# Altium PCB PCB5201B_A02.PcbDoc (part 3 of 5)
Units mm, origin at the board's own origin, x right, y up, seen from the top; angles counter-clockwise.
Board outline 115 x 60 mm, 6 copper layers (Top Layer, GND Layer 2, Signal Layer 3, Signal Layer 4, VCC Layer 5, Bottom Layer), stack 1.555 mm thick; 355 components, 250 nets, 1223 pads, 1070 vias.
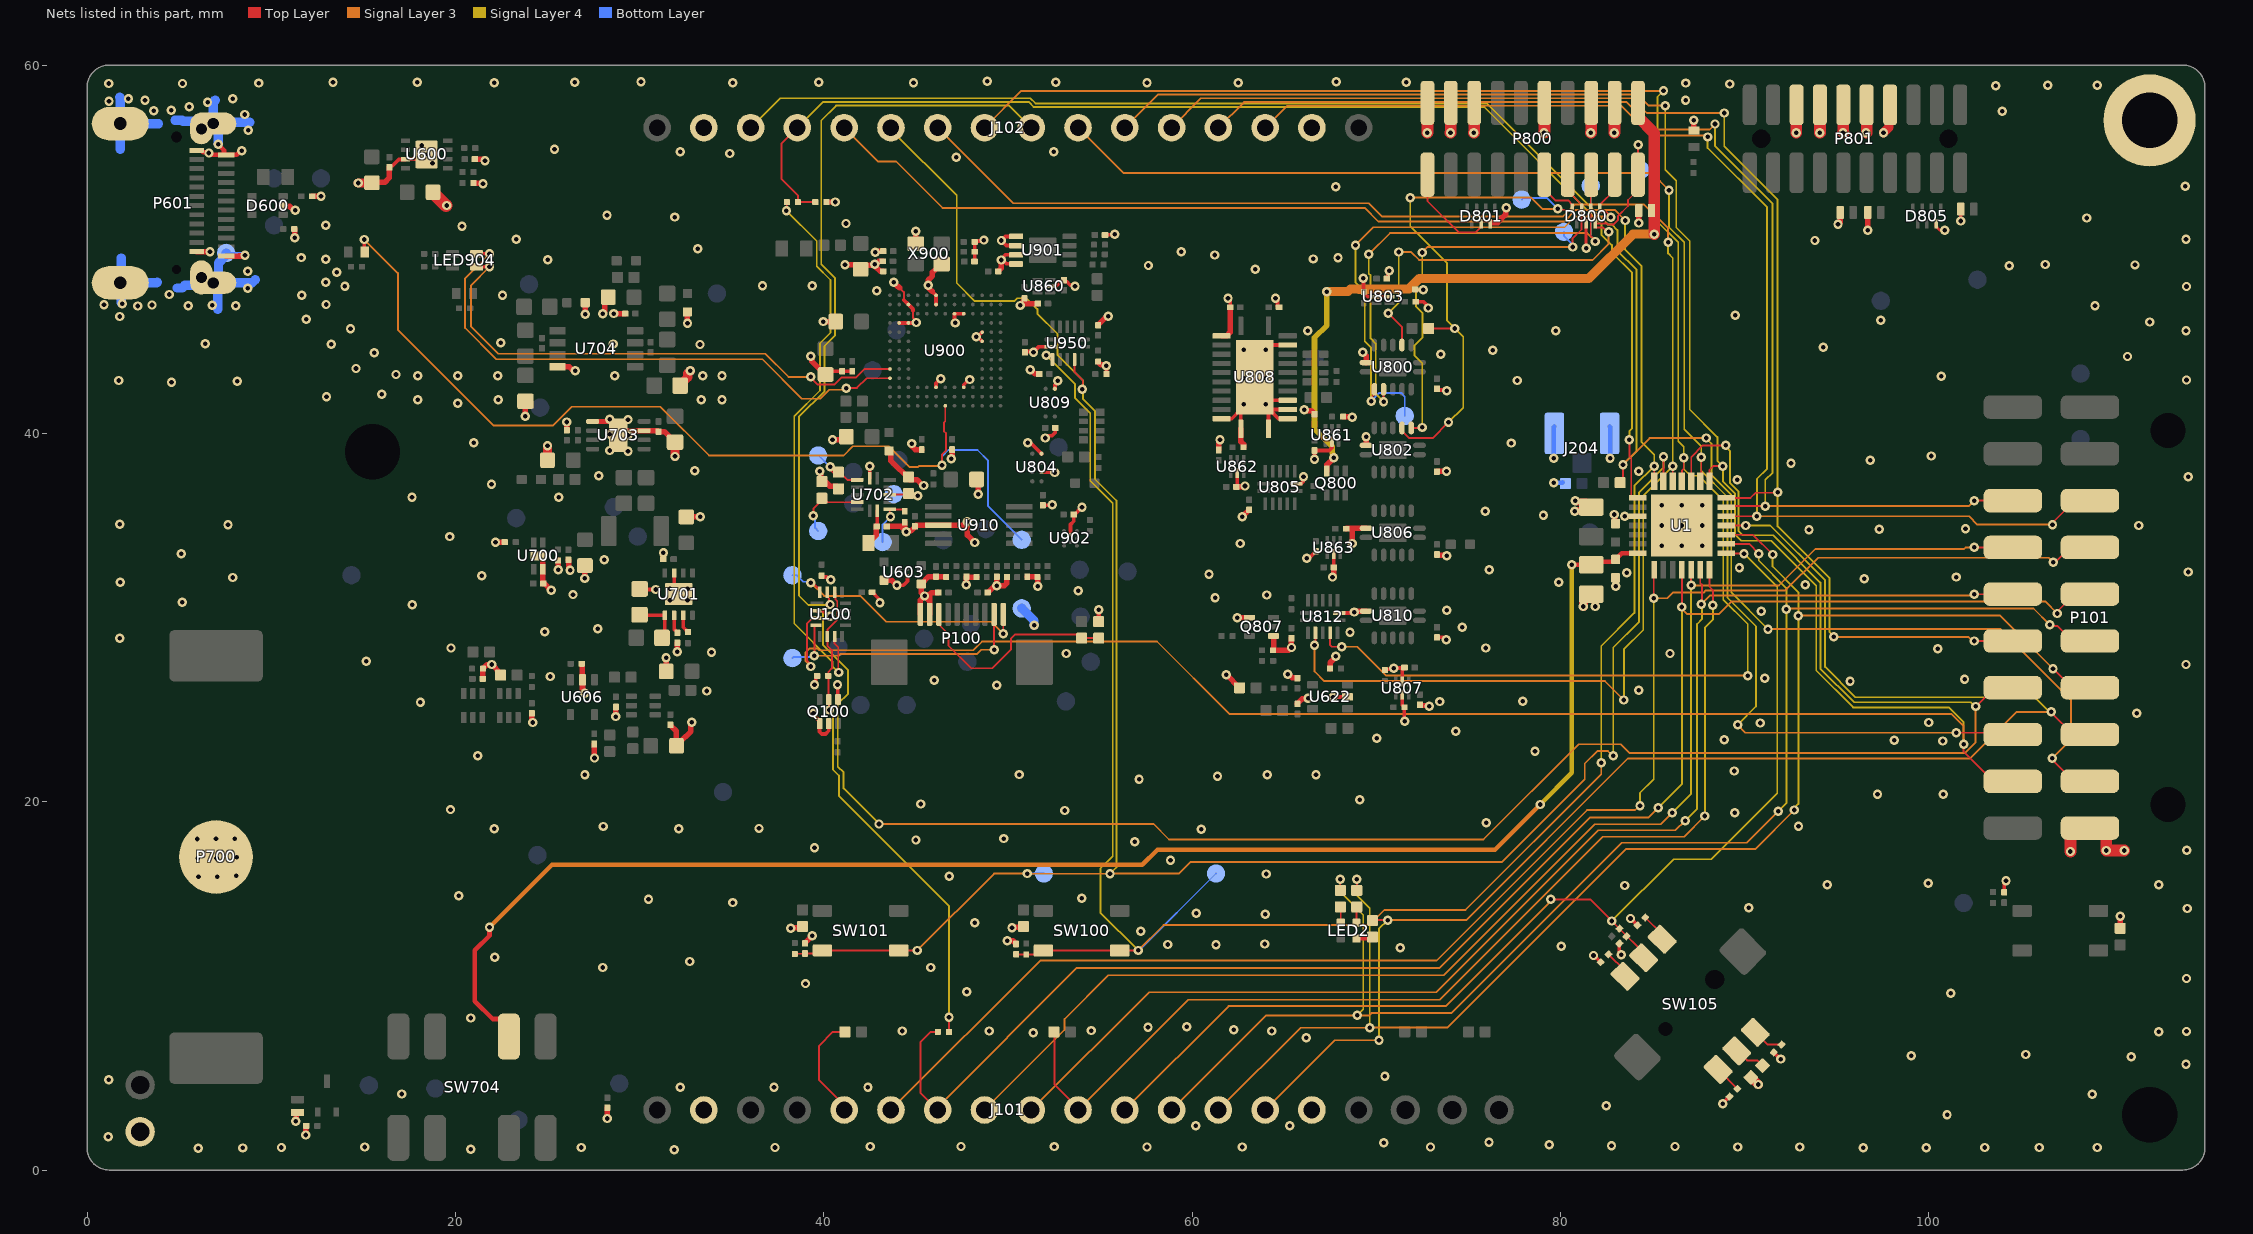
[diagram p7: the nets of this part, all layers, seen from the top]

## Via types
v1: diameter 0.508, hole 0.25, Top Layer to Bottom Layer, tented both sides, 1070 vias

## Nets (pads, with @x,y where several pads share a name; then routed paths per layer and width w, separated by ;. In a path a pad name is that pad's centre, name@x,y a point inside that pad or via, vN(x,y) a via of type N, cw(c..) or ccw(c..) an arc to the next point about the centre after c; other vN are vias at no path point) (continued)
DEBUG_TRACED3: D801.6 P800.20 | length 5.3
  Top Layer w0.1: P800.20@72.785,54.05 72.785,52.615 74.475,50.925 75.4,50.925 75.7,51.225 D801.6@75.7,51.385
DH_#RESET: D800.4 P800.10 R816.1 TPJ811.1 U802.3 | length 32.5
  Top Layer w0.1: U802.3@71.4,40.3 71.4,40.15 71.8,39.75 73.075,39.75 v1(73.925,40.6) ; R816.1@72.85,45.7 v1@74.175,45.7 ; P800.10@79.135,54.05 79.135,53.24 79.725,52.65 80.425,52.65 80.65,52.425 D800.4@80.65,52.215 80.585,52.15 79.896,52.15 v1(79.85,52.196)
  Signal Layer 3 w0.1: v1(71.85,52.807) 78.418,52.807 79.029,52.196 v1(79.85,52.196)
  Signal Layer 4 w0.1: v1(71.85,52.807) 71.85,51.25 73.85,49.25 73.85,46.125 v1(74.275,45.7) 74.725,45.25 74.725,41.4 v1(73.925,40.6)
  Bottom Layer w0.1: TPJ811.1@77.9,52.7 77.993,52.793 79.263,52.793 79.85,52.206 v1(79.85,52.196)
DH_TCK_SWCLK: D800.1 P800.4 TPJ818.1 U800.9 | length 30.3
  Top Layer w0.1: v1(69.725,41.75) 69.725,41.95 69.9,42.125 U800.9@69.9,42.4 ; v1(82.732,51.746) 82.732,51.796 82.509,52.019 82.195,52.019 82.15,52.064 82.15,52.425 82.945,53.22 P800.4@82.945,54.05
  Signal Layer 3 w0.1: v1(68.875,50.225) 69.85,51.2 80.225,51.2 80.797,51.772 82.706,51.772 v1(82.732,51.746)
  Signal Layer 4 w0.1: v1(68.875,50.225) 68.875,48.2 69.375,47.7 69.375,45 69.725,44.65 v1(69.725,41.75)
  Bottom Layer w0.1: v1(69.725,41.75) 70.175,42.2 71.35,42.2 71.55,42 TPJ818.1@71.55,40.95
DH_TDI: D800.3 P800.8 TPJ820.1 U802.2 | length 24.5
  Top Layer w0.1: U802.2@71.9,40.3 72.475,40.3 v1(72.5,40.325) ; P800.8@80.405,54.05 80.405,53.17 81.15,52.425 81.15,51.074 80.655,50.579 80.655,50.145 v1(80.675,50.125)
  Signal Layer 3 w0.1: v1(72.5,49.825) 72.8,50.125 v1(80.675,50.125)
  Signal Layer 4 w0.1: v1(72.5,40.325) 72.5,43.8 72.082,44.218 72.082,44.782 72.518,45.218 72.518,46.538 72.167,46.889 72.167,48.092 72.5,48.425 v1(72.5,49.825)
  Bottom Layer w0.1: TPJ820.1@80.2,50.95 80.2,50.71 80.675,50.235 v1(80.675,50.125)
DH_TDO_SWO: D800.2 P800.6 TPJ812.1 U800.10 | length 28.7
  Top Layer w0.1: v1@70.4,41.825 U800.10@70.4,42.4 ; P800.6@81.675,54.05 81.65,54.025 D800.2@81.65,52.215 81.65,50.746 81.9,50.496 v1(81.9,50.425)
  Signal Layer 3 w0.1: v1(69.6,49.725) 70.75,50.875 81.45,50.875 v1(81.9,50.425)
  Signal Layer 4 w0.1: v1(69.6,49.725) 69.6,48.681 69.693,48.588 69.693,45.157 69.975,44.875 69.975,42.15 v1(70.4,41.725)
  Bottom Layer w0.1: TPJ812.1@81.65,53.45 81.65,50.746 81.9,50.496 v1(81.9,50.425)
DH_TMS_SWDIO: D800.7 P800.2 TPJ814.1 U800.3 | length 26.6
  Top Layer w0.1: v1(70.663,46.527) 71.4,45.79 U800.3@71.4,44.8 ; v1(82.623,50.96) 82.524,50.96 82.295,51.189 81.945,51.189 81.9,51.234 81.9,51.445 81.945,51.4 82.525,51.4 82.572,51.353 82.898,51.353 83.128,51.583 83.128,51.803 83.675,52.35 83.675,52.675 84.215,53.215 P800.2@84.215,54.05 84.215,55.665 v1(84.225,55.675)
  Signal Layer 3 w0.1: v1(71.225,49.85) 71.899,49.85 72.331,49.418 81.752,49.418 82.623,50.289 v1(82.623,50.96)
  Signal Layer 4 w0.1: v1(70.663,46.527) 71.225,47.089 v1(71.225,49.85)
  Bottom Layer w0.1: v1(84.225,55.675) 84.225,54.425 TPJ814.1@84.35,54.3
DH_VTREF: D809.1 P800.1 Q800.3 | length 37.2
  Top Layer w0.3: Q800.3@67.325,37.95 67.325,38.3 v1(67.7,38.675)
  Top Layer w0.635: P800.1@84.215,57.95 84.215,57.193 85.1,56.309 v1(85.1,50.825)
  Signal Layer 3 w0.5: v1(67.318,47.702) 68.463,47.702 68.612,47.85 69.037,47.85 69.054,47.832 69.546,47.832 69.563,47.85 71.776,47.85 72.339,48.413 81.538,48.413 83.95,50.825 v1(85.1,50.825)
  Signal Layer 4 w0.3: v1(67.318,47.702) 67.318,45.868 66.65,45.2 66.65,40.25 67.61,39.29 67.61,38.912 67.66,38.862 67.66,38.715 v1(67.7,38.675)
  Bottom Layer w0.5: v1(67.318,47.702) v1(67.318,47.702)
DISP_CS: R301.1 U100.7 | length 30.4
  Top Layer w0.1: v1(37.975,52.1) 37.988,52.113 37.988,52.513 R301.1@38.05,52.575 ; U100.7@40.59,28.975 40.59,28.579 40.79,28.379 40.79,27.039 v1(40.807,27.021)
  Signal Layer 4 w0.1: v1(37.975,52.1) 39.625,50.45 39.625,49.075 40.368,48.332 40.368,45.468 39.799,44.899 39.799,42.332 38.4,40.933 38.4,29.677 40.47,27.607 40.47,27.358 v1(40.807,27.021)
DISP_ENABLE: Q100.2 R141.2 R303.1 U100.6 U100.14 | length 27.1
  Top Layer w0.1: v1(40.297,24.98) 40.286,24.991 40.286,25.529 40.246,25.569 40.258,25.581 40.258,26.816 R141.2@40.242,26.832 40.244,26.834 40.244,27.039 40.443,27.237 40.443,28.232 40.2,28.475 40.2,28.965 U100.6@40.19,28.975 40.208,28.993 40.208,29.358 40.737,29.887 40.737,30.888 40.64,30.985 40.64,31.325 U100.14@40.59,31.375 ; R303.1@46.8,7.5 v1(46.8,8.3)
  Signal Layer 4 w0.1: v1(40.297,24.98) 40.297,24.921 40.5,24.718 40.5,21.75 40.825,21.425 40.825,20.325 46.8,14.35 v1(46.8,8.3)
DISP_SCLK: J102.9 P101.8 U1.24 U100.15 | length 150.5
  Top Layer w0.1: U100.15@40.19,31.375 40.24,31.325 40.24,31.085 40.294,31.031 40.294,30.758 v1(40.344,30.709) ; U1.24@87.1,37.275 87.113,37.287 87.113,38.718 87.744,39.35 v1(88.975,39.35) ; v1(102.55,25.175) 102.576,25.175 103.591,26.19 P101.8@104.57,26.19
  Signal Layer 3 w0.1: v1(43.003,18.793) 57.907,18.793 58.75,17.95 75.825,17.95 80.993,23.118 83.282,23.118 83.75,22.65 101.981,22.65 102.55,23.219 v1(102.55,25.175)
  Signal Layer 4 w0.1: v1@40.313,30.678 39.172,30.678 38.65,31.2 38.65,40.9 40.05,42.3 40.05,44.75 40.62,45.32 40.62,48.43 39.866,49.184 39.866,56.991 40.675,57.8 50.072,57.8 J102.9@51.27,56.602 ; v1(40.344,30.709) 39.951,30.316 39.951,28.524 41.325,27.15 41.325,25.875 40.763,25.313 40.763,21.912 41.075,21.6 41.075,20.721 v1(43.003,18.793) ; v1(88.975,39.35) 88.975,39.264 89.218,39.022 89.218,38.062 89.207,38.051 89.207,37.312 89.682,36.837 89.682,34.693 89.9,34.475 91.55,34.475 94.125,31.9 94.125,27.225 95.95,25.4 102.287,25.4 102.512,25.175 v1(102.55,25.175)
DISP_SI: J102.11 P101.4 U1.22 U100.3 | length 151
  Top Layer w0.1: 39.24,29.825 39.1,29.685 39.1,27.656 39.304,27.452 v1(39.304,27.342) ; 39.24,29.825 39.39,29.975 U100.3@39.59,29.975 ; U1.22@88.1,37.275 88.1,38.025 88.3,38.225 v1@88.75,38.225 ; v1(101.9,23.125) 101.9,22.725 103.515,21.11 P101.4@104.57,21.11
  Signal Layer 3 w0.1: v1(39.304,27.342) 39,27.645 39,28.1 39.218,28.318 39.671,28.318 39.764,28.225 48.125,28.225 48.6,28.7 58.098,28.7 62.028,24.769 101.231,24.769 101.9,24.1 v1(101.9,23.125) ; J102.11@56.35,56.602 58.146,58.398 84.202,58.398 84.8,57.8 v1(85.7,57.8)
  Signal Layer 4 w0.1: v1(85.7,57.8) 85.7,54.317 86.293,53.724 86.293,51.182 87.025,50.45 87.025,41.3 88.525,39.8 88.525,38.525 v1(88.825,38.225) 88.825,37.412 89.482,36.754 89.482,34.518 89.825,34.175 91.456,34.175 93.9,31.731 93.9,27.125 95.9,25.125 101.1,25.125 101.9,24.325 v1(101.9,23.125)
EFM_VREGIN: C3.1 C4.1 SW704.7 U1.7 | length 84.7
  Top Layer w0.25: v1(21.85,13.175) 21.85,12.725 21.05,11.925 21.05,9.175 22.023,8.202 22.438,8.202 22.9,7.741 SW704.7@22.9,7.25 ; v1(80.625,32.875) 80.628,32.872 81.672,32.872 C3.1@81.675,32.869 ; C3.1@81.725,33.1 81.788,33.037 82.875,33.037 C4.1@83,33.162 83.338,33.5 U1.7@84.325,33.5
  Signal Layer 3 w0.25: v1(21.85,13.175) 25.243,16.568 57.293,16.568 58.125,17.4 76.45,17.4 v1(78.9,19.85)
  Signal Layer 4 w0.25: v1(78.9,19.85) 80.625,21.575 v1(80.625,32.875)
EXP_HEADER5: J101.14 P101.5 R135.2 U1.18 | length 83.4
  Top Layer w0.1: R135.2@69.8,13.55 69.85,13.6 69.878,13.572 v1(70.628,13.572) ; U1.18@88.875,35 v1(90.075,35) ; v1(106.658,24.881) 106.658,24.84 107.848,23.65 P101.5@108.76,23.65
  Signal Layer 3 w0.1: J101.14@63.97,3.262 67.758,7.05 v1(70.15,7.05) ; v1(70.628,13.572) 74.897,13.572 83.675,22.35 102.25,22.35 104.781,24.881 v1(106.658,24.881)
  Signal Layer 4 w0.1: v1(70.15,7.05) 70.15,13.094 v1(70.628,13.572) ; v1(90.075,35) 91.4,35 94.375,32.025 94.375,27.325 96.025,25.675 105.75,25.675 106.466,24.959 106.469,24.959 v1@106.6,24.828
EXP_HEADER6: J102.10 P101.6 U1.23 | length 81.5
  Top Layer w0.1: U1.23@87.6,37.275 87.65,37.325 v1(87.65,38.7) ; v1(101.5,23.75) 104.47,23.75 P101.6@104.57,23.65
  Signal Layer 3 w0.1: J102.10@53.81,56.602 56.262,54.15 84.957,54.15 v1(85.9,53.207) ; v1(89.625,24.175) 90.052,23.748 101.498,23.748 v1(101.5,23.75)
  Signal Layer 4 w0.1: v1(85.9,53.207) 85.9,51.2 86.725,50.375 86.725,40.225 87.65,39.3 v1(87.65,38.7) 87.65,37.975 89.077,36.548 89.077,31.073 90.625,29.525 90.625,25.175 v1(89.625,24.175)
EXP_HEADER7: J101.13 P101.7 R136.2 U1.17 | length 82.1
  Top Layer w0.1: R136.2@68.944,15.184 68.95,15.191 v1(68.95,15.8) ; U1.17@88.875,34.5 90.45,34.5 v1(91.525,33.425) ; v1(106.753,27.229) 106.761,27.229 107.8,26.19 P101.7@108.76,26.19
  Signal Layer 3 w0.1: J101.13@61.43,3.262 65.893,7.725 v1(69.65,7.725) 69.657,7.732 73.857,7.732 83.55,17.425 90.575,17.425 v1(92.7,19.55) ; v1(92.925,30.1) 92.943,30.118 103.864,30.118 v1(106.753,27.229)
  Signal Layer 4 w0.1: v1(68.95,15.8) 68.95,14.925 69.65,14.225 v1(69.65,7.725) ; v1(91.525,33.425) 91.525,32.775 92.925,31.375 v1(92.925,30.1) 92.925,19.885 92.7,19.66 v1(92.7,19.55)
EXP_HEADER9: J101.12 P101.9 R137.2 U1.16 | length 82.4
  Top Layer w0.1: v1(68.05,15.8) 68.05,15.189 R137.2@68.052,15.187 ; U1.16@88.875,34 90.25,34 v1(90.775,33.475) ; v1(106.584,29.602) 106.636,29.55 106.988,29.55 107.808,28.73 P101.9@108.76,28.73
  Signal Layer 3 w0.1: J101.12@58.89,3.262 64.028,8.4 v1(68.975,8.4) v1@69,8.4 ; v1@69.05,8.4 69.625,8.4 69.75,8.525 74.075,8.525 83.325,17.775 90.125,17.775 v1(91.825,19.475) ; v1(92.275,30.45) 92.318,30.493 105.693,30.493 v1(106.584,29.602)
  Signal Layer 4 w0.1: v1(68.05,15.8) 68.05,15.1 69.3,13.85 69.3,8.725 v1(68.975,8.4) ; v1(90.775,33.475) 90.775,33.1 92.275,31.6 v1(92.275,30.45) 92.275,19.925 v1(91.825,19.475)
EXP_HEADER10: J102.12 P101.10 U1.21 | length 74.8
  Top Layer w0.1: U1.21@88.875,36.5 90.325,36.5 90.6,36.775 91.775,36.775 v1(91.8,36.8) ; v1(102.47,28.73) P101.10@104.57,28.73
  Signal Layer 3 w0.1: J102.12@58.89,56.602 60.485,58.197 83.903,58.197 84.7,57.4 v1(88.9,57.4) ; v1(94.85,28.95) 102.14,28.95 102.36,28.73 v1(102.47,28.73)
  Signal Layer 4 w0.1: v1(88.9,57.4) 88.9,55.595 91.8,52.695 v1(91.8,36.8) 91.8,34.95 94.625,32.125 94.625,29.213 94.85,28.988 v1(94.85,28.95)
EXP_HEADER11: J101.7 P101.11 R303.2 U1.11 | length 88.3
  Top Layer w0.1: J101.7@46.19,3.262 45.25,4.202 45.25,6.95 45.8,7.5 R303.2@46.2,7.5 ; v1(86.6,30.575) U1.11@86.6,32.725 ; v1(106.977,30.222) 106.977,30.331 107.916,31.27 P101.11@108.76,31.27
  Signal Layer 3 w0.1: J101.7@46.19,3.262 46.19,3.415 53.75,10.975 73.45,10.975 81.625,19.15 84.8,19.15 v1(85.325,19.675) ; v1(86.6,30.575) 86.6,30.467 86.867,30.2 88.625,30.2 89.3,30.875 106.324,30.875 v1(106.977,30.222)
  Signal Layer 4 w0.1: v1(85.325,19.675) 86.6,20.95 v1(86.6,30.575)
EXP_HEADER12: J101.9 P101.12 U1.13 | length 73.4
  Top Layer w0.1: U1.13@87.6,32.725 87.6,31.875 87.7,31.775 87.7,30.775 v1(87.65,30.725) ; v1(102.47,31.27) P101.12@104.57,31.27
  Signal Layer 3 w0.1: J101.9@51.27,3.262 57.665,9.657 73.257,9.657 82.05,18.45 86.25,18.45 v1(86.775,18.975) ; v1(87.65,30.725) 88.117,31.192 102.392,31.192 v1(102.47,31.27)
  Signal Layer 4 w0.1: v1(86.775,18.975) 87.425,19.625 87.425,29.65 87.7,29.925 87.7,30.675 v1(87.65,30.725)
EXP_HEADER13: J101.6 P101.13 U1.8 | length 85.8
  Top Layer w0.1: v1(85.075,31.05) 85.075,32.7 U1.8@85.1,32.725 ; v1(106.775,33) 106.885,33 107.745,33.86 P101.13@108.8,33.86
  Signal Layer 3 w0.1: J101.6@43.65,3.262 51.763,11.375 73.275,11.375 81.45,19.55 84.062,19.55 84.287,19.775 v1(84.325,19.775) ; v1@85.2,31.025 85.225,31.05 85.8,31.05 86.107,31.357 87.782,31.357 87.9,31.475 92.225,31.475 94,33.25 106.525,33.25 v1(106.775,33)
  Signal Layer 4 w0.1: v1(84.325,19.775) 84.325,20.48 85.075,21.23 v1(85.075,31.05)
EXP_HEADER14: J101.8 P101.14 U1.12 | length 76.4
  Top Layer w0.1: v1(87.1,31.75) U1.12@87.1,32.725 ; v1(102.47,33.81) P101.14@104.57,33.81
  Signal Layer 3 w0.1: J101.8@48.73,3.262 53.075,7.607 53.075,8.2 55.45,10.575 73.675,10.575 81.875,18.775 85.45,18.775 v1(86.075,19.4) ; v1(87.1,31.75) 91.875,31.75 93.85,33.725 101.925,33.725 102.01,33.81 v1(102.47,33.81)
  Signal Layer 4 w0.1: v1(86.075,19.4) 87.1,20.425 v1@87.1,31.7
EXP_HEADER15: J102.14 P101.15 U1.19 | length 68.1
  Top Layer w0.1: U1.19@88.875,35.5 v1(90.675,35.5) ; v1(106.725,35.05) 106.725,35.159 107.966,36.4 P101.15@108.8,36.4
  Signal Layer 3 w0.1: J102.14@63.97,56.602 65.162,57.794 83.306,57.794 84.922,56.178 87.922,56.178 v1(88,56.1) ; v1(90.675,35.5) 102.2,35.5 102.65,35.05 v1(106.725,35.05)
  Signal Layer 4 w0.1: v1(88,56.1) 88,55.5 91.225,52.275 91.225,38.075 90.675,37.525 v1(90.675,35.5)
EXP_HEADER16: J102.13 P101.16 U1.20 | length 66.3
  Top Layer w0.1: U1.20@88.875,36 88.925,36.05 v1(91.125,36.05) ; v1(102.47,36.35) P101.16@104.57,36.35
  Signal Layer 3 w0.1: J102.13@61.43,56.602 62.823,57.995 83.605,57.995 85.1,56.5 88.1,56.5 v1(88.4,56.8) ; v1(91.125,36.05) 102.17,36.05 v1(102.47,36.35)
  Signal Layer 4 w0.1: v1(88.4,56.8) 88.4,55.6 91.525,52.475 91.525,37.875 91.125,37.475 v1(91.125,36.05)
GND: C1.2 C2.2 C3.2 C4.2 C8.2 C102.2 C103.2 C104.2 C106.2 C143.2 C144.2 C600.2 C602.2 C607.2 C608.2 C609.2 C610.2 C611.2 C621.2 C625.2 C632.2 C635.2 C638.2 C641.2 C652.2 C653.2 C655.2 C660.2 C673.2 C674.2 C700.2 C701.2 C702.2 C703.2 C705.2 C706.2 C707.2 C708.2 C714.2 C720.2 C724.2 C728.2 C729.2 C730.2 C731.2 C800.2 C803.2 C804.2 C805.2 C806.2 C807.2 C808.2 C809.2 C810.2 C827.2 C828.2 C860.2 C861.2 C862.2 C863.2 C864.2 C865.2 C866.2 C867.2 C868.2 C869.2 C870.2 C900.2 C901.2 C902.2 C903.2 C904.2 C905.2 C906.2 C907.2 C908.2 C909.2 C910.2 C911.2 C914.2 C921.2 C922.2 C924.2 C925.2 C926.2 C927.2 C950.2 C951.2 D600.2 D703.2 D800.6 D801.7 D805.7 D806.2 D807.2 D808.2 D809.2 J101.2 J101.15 J102.2 J102.15 J204.2 J204.3 LED900.2 M1.1 P100.1 P100.2 P101.1 P601.25@1.8,56.82 P601.26@1.8,48.18 P601.27@6.2,56.525 P601.27@6.85,56.82 P601.28@6.2,48.475 P601.28@6.85,48.18 P601.A1 P601.A12 P601.B1 P601.B12 P700.2 P800.3 P800.5 P800.9 P800.15 P800.17 P800.19 P801.7 P801.9 P801.11 P801.13 P801.15 Q100.1 Q100.4 Q100.5 Q807.1 Q807.4 R7.1 R104.2 R105.2 R113.1 R124.1 R125.1 R126.1 R127.1 R140.1 R141.1 R146.1 R220.1 R302.1 R602.1 R620.1 R621.1 R623.1 R628.2 R631.1 R634.1 R637.1 R640.1 R674.2 R688.2 R691.2 R703.1 R705.1 R706.1 R707.1 R708.1 R718.1 R760.1 R763.1 R767.1 R771.1 R792.1 R807.2 R808.2 R814.1 R817.1 R839.1 R850.1 R851.1 R852.1 R853.1 R930.2 R931.2 R950.2 R981.2 ST701.1 TPJ614.1 TPJ913.1 U1.3 U1.29 U100.2 U600.3 U600.9 U603.A1 U606.2 U622.2 U700.2 U700.5 U701.3 U701.9 U702.7 U703.3 U703.5 U703.9 U704.4 U800.7 U802.7 U803.2 U803.5 U804.B1 U804.D1 U805.7 U806.7 U807.2 U807.5 U808.2 U808.11 U808.12 U808.13 U808.14 U808.15 U808.16 U808.22 U808.25 U809.D1 U810.7 U812.7 U860.2 U861.2 U862.2 U863.2 U900.C5 U900.C8 U900.H3 U900.J3 U900.K11 U900.K12 U900.L5 U900.L6 U900.M8 U900.M11 U900.N8 U901.1 U901.2 U901.3 U901.4 U902.B2 U910.3 U950.7 X900.2 X900.4 | length 231.3
  Top Layer w0.1: 44.125,47.9 44.35,47.675 44.35,47.25 ; 44.85,46.674 44.85,46.275 v1@45.025,46.1
  Top Layer w0.15: v1(81.4,50.05) D800.6@81.4,51.385 ; D805.7@100.4,51.385 100.4,51.25 100.6,51.05 v1@101.05,51.05
  Top Layer w0.2: C600.2@16.417,54.451 16.417,54.471 16.477,54.531 16.581,54.531 16.922,54.872 17.257,54.872 U600.3@17.282,54.897 U600.9@18.182,54.897 ; R703.1@30.105,31.556 30.135,31.525 v1(30.875,31.525) ; U701.9@31.725,31.575 31.875,31.725 U701.3@31.875,32.425 ; v1(39.446,24.8) 39.446,24.719 39.775,24.39 Q100.4@39.775,24.24 39.775,23.8 39.9,23.675 40.1,23.675 40.275,23.85 Q100.5@40.275,24.24 ; v1(39.498,26.353) 39.498,26.437 39.572,26.511 39.572,26.772 39.632,26.832 R141.1@39.642,26.832 ; U100.2@39.59,30.375 39.956,30.375 40.261,30.07 v1(40.344,30.07) ; R140.1@39.888,32.275 39.888,32.265 39.948,32.205 40.158,32.205 40.307,32.057 v1(40.39,32.057) ; C907.2@40.1,43.2 40.275,43.375 C924.2@41,43.375 C925.2@41.55,43.375 ; v1(40.75,26.35) 40.762,26.337 40.762,25.552 Q100.1@40.775,25.54 ; U702.7@42.5,37.56 v1(42.5,38.225) v1@42.65,38.225 ; C104.2@42.623,31.374 42.643,31.374 42.993,31.024 42.993,30.863 v1(43.052,30.804) ; v1(43.975,31.75) 44.325,31.75 44.55,31.975 U603.A1@44.55,32.25 ; U900.K12@44.1,46 U900.K11@44.6,46 45,46 v1(45.025,46.025) v1@45.025,46.1 ; 44.35,47.25 U900.M11@44.6,47 44.85,46.75 44.85,46.674 ; v1@45.35,37.1 v1(45.425,37.175) ; 45.885,47.71 46.095,47.5 U900.N8@46.1,47.5 U900.M8@46.1,47 ; U900.C8@46.1,42.5 46.1,42.725 v1(46.35,42.975) ; v1(47.15,46) 47.1,46.05 U900.L6@47.1,46.5 U900.L5@47.6,46.5 ; U900.C5@47.6,42.5 47.6,42.65 v1@47.875,42.925 ; C910.2@48.184,49.333 48.193,49.342 48.193,49.857 R930.2@48.201,49.865 ; R930.2@48.202,49.863 R930.2@48.201,49.865 ; v1@48.224,45.25 v1(48.275,45.25) 48.3,45.25 v1@48.325,45.275 ; U900.H3@48.6,45 v1@48.325,45.275 ; U900.J3@48.6,45.5 48.375,45.275 v1@48.325,45.275 ; v1(48.7,50.5) 48.65,50.45 48.25,50.45 R931.2@48.2,50.4 48.201,50.399 R930.2@48.201,49.865 ; v1@49.65,49.4 49.733,49.4 49.923,49.21 50.434,49.21 U901.4@50.445,49.2 ; v1@49.65,49.483 49.867,49.7 U901.3@50.445,49.7 ; U901.2@50.445,50.2 50.436,50.208 49.917,50.208 v1(49.65,50.475) 49.867,50.692 50.436,50.692 U901.1@50.445,50.7 ; C911.2@50.925,44.4 50.95,44.375 50.993,44.375 51.068,44.45 51.355,44.45 v1(51.392,44.413) ; v1@51.225,39.45 51.275,39.45 U804.D1@51.825,38.9 ; v1@51.4,44.45 51.413,44.45 51.663,44.7 U950.7@52.34,44.7 ; U804.B1@51.825,37.9 52.525,37.9 v1(52.55,37.875) ; C804.2@51.9,36.1 52.375,36.1 v1(52.4,36.125) ; v1(52.025,39.75) 52.15,39.875 52.4,39.875 52.575,40.05 C810.2@52.575,40.3 ; U860.2@52.3,48 52.625,48 52.95,48.325 C862.2@53.05,48.325 53.05,48.305 53.11,48.245 53.194,48.245 53.391,48.048 53.586,48.048 v1(53.645,47.989) ; U809.D1@52.55,42.425 52.556,42.431 52.556,42.63 52.709,42.784 v1(52.709,42.867) ; U902.B2@53.4,34.5 53.4,35.05 53.575,35.225 C914.2@53.575,35.55 ; C914.2@53.575,35.6 C914.2@53.575,35.55 ; v1(54.025,36) C914.2@53.575,35.55 ; C951.2@55.272,50.778 55.29,50.796 55.787,50.796 v1(55.805,50.814) ; R981.2@55.35,43.225 v1(55.35,43.679) ; U808.11@61.605,40.8 62.15,40.8 U808.25@62.65,41.3 ; v1(61.95,47.35) 62.075,47.225 C808.2@62.075,46.85 ; C860.2@62.4,37.1 62.45,37.15 U862.2@62.45,37.85 ; U808.12@62.65,40.255 U808.25@62.65,41.3 ; U808.25@63.425,44.55 63.675,44.8 U808.22@65.195,44.8 ; U808.13@64.15,40.255 U808.25@64.15,41.3 ; v1(64.532,47.345) 64.532,47.275 64.645,47.162 64.645,46.91 64.705,46.85 C806.2@64.725,46.85 ; U808.14@65.195,40.8 64.7,40.8 U808.25@64.2,41.3 ; U808.15@65.195,41.3 U808.25@64.2,41.3 ; U808.16@65.195,41.8 63.625,41.8 U808.25@63.4,41.575 ; U805.7@65.66,37.27 65.92,37.27 66.025,37.375 66.025,37.625 v1(66.05,37.65) ; v1(66.225,33.225) 66.35,33.225 C867.2@66.725,33.6 ; v1(66.65,38.6) C864.2@66.65,39.075 67.45,39.075 67.6,39.225 U861.2@67.6,39.55 ; v1(67.657,25.682) 67.666,25.691 68.441,25.691 U622.2@68.45,25.7 ; C866.2@67.7,32.725 U863.2@67.7,33.45 ; U812.7@67.985,30.25 68.75,30.25 v1(68.8,30.3) ; v1(69.3,48.425) 69.313,48.413 69.313,47.687 R807.2@69.325,47.675 ; R807.2@69.385,47.59 69.55,47.425 U803.2@70.025,47.425 ; U803.2@70.075,47.425 U803.5@70.725,47.425 ; R808.2@70.475,27.15 70.525,27.2 70.825,27.2 v1@70.875,27.25 ; C869.2@70.569,48.403 70.581,48.403 70.641,48.463 70.641,48.766 v1(70.7,48.825) ; v1(70.95,27.25) 70.967,27.267 71.522,27.267 C870.2@71.539,27.284 ; U807.5@71.413,25.825 71.413,25.239 71.502,25.15 R814.1@71.55,25.15 ; U807.2@71.413,26.525 71.413,27.178 71.46,27.225 C870.2@71.55,27.225 ; R814.1@71.532,25.13 71.532,24.395 v1(71.55,24.377) ; C807.2@72.125,47.825 72.14,47.81 72.545,47.81 v1(72.56,47.795) ; R817.1@72.15,47.15 72.566,47.15 72.825,46.891 v1(72.825,46.81) ; C827.2@73.3,28.925 73.675,28.925 v1(73.8,28.8) ; C803.2@73.3,42.425 73.3,42.421 73.36,42.361 73.789,42.361 v1(73.825,42.325) ; v1@73.802,37.938 v1(73.816,37.951) ; v1(81.8,11.65) 81.826,11.65 R124.1@82.188,11.288 ; C106.2@83.206,12.306 83.206,11.794 v1(83.3,11.7) ; v1(83.807,13.657) 83.833,13.657 R127.1@84.195,13.295 ; v1(88.826,3.6) 88.826,3.626 R125.1@89.188,3.988 ; R126.1@91.588,6.388 91.95,6.026 v1(91.976,6.026) ; v1@101.749,51.534 D808.2@101.748,52.181 ; C8.2@104.1,15.075 104.1,15.6 v1(104.2,15.7) ; U808.25@62.65,41.3 62.925,41.575 U808.25@63.4,41.575 ; U808.25@63.4,41.575 63.675,41.3 U808.25@64.15,41.3 ; U808.25@64.15,41.3 U808.25@64.2,41.3
  Top Layer w0.25: P601.B12@5.95,55.375 5.96,55.365 6.225,55.365 6.313,55.277 6.566,55.277 v1(6.615,55.227) ; v1@6.658,55.178 6.735,55.178 6.777,55.135 P601.A1@7.432,55.135 ; v1(7.128,55.71) 7.128,55.689 7.432,55.385 P601.A1@7.432,55.135 ; v1(8.398,55.347) 8.328,55.347 8.116,55.135 7.56,55.135 P601.A1@7.55,55.125 ; U703.5@27.45,40.65 v1@28.25,40.65 ; R302.1@40.146,52.564 40.148,52.566 40.616,52.566 v1(40.619,52.569) 40.55,52.638 v1@40.55,52.65 ; v1@54.925,30.4 54.933,30.392 54.933,29.783 R146.1@54.932,29.782 ; C868.2@72.376,25.263 72.411,25.228 72.839,25.228 v1(72.875,25.192) ; C3.2@81.25,30.919 81.6,31.269 C3.2@81.675,31.269 ; C1.2@81.699,35.824 C1.2@82.075,36.2 ; C3.2@81.9,31.1 C3.2@81.925,31.125 ; v1(83,31.7) C4.2@83,32.162 ; v1(83.5,35.5) U1.3@84.325,35.5 ; P601.A1@7.432,55.135 7.54,55.135 P601.A1@7.55,55.125 ; P601.A1@7.432,55.135 7.442,55.125 P601.A1@7.55,55.125
  Top Layer w0.27: v1@77.057,52.195 v1(77.057,52.251)
  Top Layer w0.3: P601.B1@5.95,49.875 v1(6.675,49.875) ; P601.A12@7.55,49.625 8.25,49.625 8.26,49.635 8.535,49.635 v1(8.575,49.675) ; D600.2@10.647,52.374 10.684,52.336 10.993,52.336 11.207,52.122 v1(11.298,52.122) ; R621.1@11.25,51.1 11.252,51.1 11.262,51.09 11.262,50.637 v1(11.275,50.625) ; v1(11.325,2.65) 11.365,2.69 11.365,3.075 11.415,3.125 D703.2@11.425,3.125 ; v1(11.875,1.9) 11.883,1.908 11.883,2.39 11.893,2.4 R792.1@11.9,2.4 ; R620.1@12.224,52.88 12.226,52.878 12.697,52.878 v1(12.7,52.875) ; C611.2@15.525,53.55 15.614,53.639 16.164,53.639 16.417,53.892 C600.2@16.417,54.451 ; R602.1@20.982,53.597 20.982,53.587 20.992,53.577 21.472,53.577 v1(21.498,53.552) ; C602.2@21.057,54.897 21.507,54.897 v1(21.607,54.797) ; C610.2@21.475,26.675 21.475,27.2 R623.1@21.5,27.225 21.725,27.45 v1(21.975,27.45) 22.45,26.975 R628.2@22.45,26.875 ; v1(22.175,34.1) v1(22.175,34.1) 22.678,34.099 R763.1@22.679,34.098 ; v1(23.8,40.925) R767.1@23.8,41.75 ; C621.2@24.15,24.8 24.15,24.35 v1(24.2,24.3) ; U700.5@24.5,33.35 24.65,33.35 24.75,33.25 U700.2@24.75,32.625 24.75,31.875 C708.2@24.775,31.85 24.825,31.85 v1(25.2,31.475) ; U704.4@25.545,43.625 26.175,43.625 26.4,43.4 v1(26.5,43.4) ; R760.1@25.573,33.103 R760.1@25.573,33.103 v1(25.575,32.6) v1(25.575,32.6) ; v1(26.046,40.62) 26.048,40.618 26.048,40.177 C728.2@26.05,40.175 ; C701.2@26.134,33.137 26.144,33.127 26.144,32.713 26.225,32.631 v1(26.225,32.575) ; R674.2@26.86,27.49 26.87,27.49 26.88,27.48 26.88,26.645 U606.2@26.9,26.625 26.9,26.025 v1(27.025,25.9) ; v1(27.025,32.125) 27.029,32.129 27.029,32.821 C700.2@27.033,32.825 ; v1(27.05,46.475) C720.2@27.05,47.1 ; C660.2@27.537,23.135 27.544,23.128 27.544,22.381 v1(27.55,22.375) ; v1(28,46.5) 28.1,46.6 28.1,47.2 C731.2@28.3,47.4 ; v1@28.25,2.8 C706.2@28.25,3.375 ; v1@28.25,40.65 v1(28.375,40.775) ; v1(28.597,46.509) C730.2@29.222,46.509 ; v1(28.7,24.625) 28.706,24.631 28.706,25.14 C674.2@28.713,25.147 ; U703.9@28.85,39.9 U703.9@29.1,40.15 ; v1(29.373,40.753) 29.334,40.713 29.334,40.65 29.2,40.65 29.1,40.55 U703.9@29.1,40.15 ; C702.2@31.295,33.171 v1(31.295,33.521) ; v1(31.438,27.822) 31.443,27.817 31.443,27.085 C625.2@31.448,27.08 ; C673.2@31.685,24.145 32.004,23.826 C655.2@32.004,23.061 ; R718.1@31.925,39.525 31.35,40.1 C729.2@31.025,40.1 30.975,40.15 U703.3@30.25,40.15 U703.9@29.1,40.15 ; C655.2@32.004,23.036 C655.2@32.004,23.061 ; v1(32.05,28.15) C705.2@32.05,28.629 ; C703.2@32.535,35.461 32.542,35.468 33.293,35.468 v1(33.3,35.475) ; v1(32.6,45.975) C724.2@32.6,46.6 ; v1(32.826,24.318) 32.787,24.278 32.787,23.819 32.493,23.526 32.468,23.526 C655.2@32.004,23.061 ; v1@38.15,13.15 38.165,13.165 38.79,13.165 R105.2@38.85,13.225 ; v1(38.2,13.125) v1@38.225,13.15 ; C103.2@38.986,12.306 38.986,12.326 39.373,12.713 v1(39.382,12.713) ; v1(39.304,44.196) 39.343,44.156 39.343,43.932 40.075,43.2 C907.2@40.1,43.2 ; v1(39.793,37.95) 39.793,37.894 39.843,37.844 39.843,37.529 R705.1@39.993,37.379 ; v1(39.975,46.075) C900.2@40.65,46.075 ; R705.1@40.125,37.35 40.125,37.247 40.143,37.229 40.246,37.229 40.331,37.144 40.72,37.144 R706.1@40.87,36.994 ; v1(40.475,39.65) 41.05,39.65 C902.2@41.225,39.825 ; v1(41.156,49.165) 41.756,49.165 C903.2@42.006,48.915 ; C903.2@42.1,49 42.229,49.129 42.723,49.129 v1(42.777,49.183) ; v1(42.804,49.833) 42.861,49.833 42.914,49.886 43.213,49.886 C906.2@43.223,49.896 ; C905.2@43.21,49.352 43.2,49.342 42.992,49.342 42.834,49.183 v1(42.777,49.183) ; C904.2@43.223,48.802 43.213,48.812 43.057,48.812 42.817,49.052 42.817,49.143 v1(42.777,49.183) ; C609.2@43.275,32.025 43.7,32.025 v1(43.975,31.75) ; C707.2@43.425,34.95 44.193,34.95 v1@44.396,34.747 ; C901.2@43.55,39.05 43.65,38.95 43.65,38.512 44.673,37.489 45.054,37.489 45.369,37.175 v1(45.425,37.175) ; v1(43.8,48.2) 44,48 44.025,48 44.125,47.9 ; R708.1@44.4,35.175 44.4,35.159 44.396,35.155 v1@44.396,34.747 ; v1(44.476,34.667) v1@44.396,34.747 ; v1@44.5,34.6 44.5,34.635 44.572,34.707 44.727,34.707 44.95,34.93 C922.2@44.95,34.95 ; v1(44.775,39.45) 44.775,39.325 44.975,39.125 C927.2@45.325,39.125 ; C922.2@44.94,34.94 C922.2@44.95,34.95 ; X900.4@45,50.3 v1(45,50.975) ; P100.1@45.25,30.175 45.25,30.95 v1(45.475,31.175) ; v1@45.675,48.05 45.675,48.325 45.9,48.551 45.9,48.75 46.35,49.2 X900.2@46.4,49.2 ; v1(45.675,48.05) 45.675,47.92 45.885,47.71 ; P100.2@45.75,30.175 45.75,30.9 ; C143.2@46.224,31.364 46.214,31.354 45.854,31.354 45.75,31.25 ; R637.1@46.65,32.2 46.625,32.225 C638.2@46.1,32.225 45.7,32.225 C608.2@45.3,31.825 45.3,31.35 v1(45.475,31.175) ; v1@46.975,38.625 C926.2@46.975,39.125 ; v1(47.742,31.782) v1@47.746,31.786 ; v1@47.782,31.822 v1@47.746,31.786 ; v1@47.825,35.225 v1(47.8,35.2) ; v1(48.2,34.075) 47.8,34.475 v1(47.8,35.2) ; R640.1@48.29,32.18 48.29,32.19 R640.1@48.3,32.2 47.775,32.2 C641.2@47.75,32.225 47.746,32.221 v1@47.746,31.786 ; C921.2@48.3,37.5 48.4,37.4 v1(48.4,36.7) ; C144.2@48.9,31.368 48.92,31.368 49.236,31.685 49.36,31.685 v1(49.4,31.725) ; C635.2@49.4,32.225 v1(49.4,31.725) ; C908.2@49.475,48.8 49.65,48.975 49.65,49.4 v1(49.634,49.416) ; R634.1@49.95,32.2 49.95,31.875 49.8,31.725 v1(49.4,31.725) ; v1(49.975,12.45) 50.275,12.45 C102.2@50.45,12.275 ; v1@50.225,13.125 50.285,13.185 50.812,13.185 R104.2@50.847,13.22 ; R850.1@50.9,47.342 50.89,47.332 50.89,47.221 50.675,47.006 v1(50.675,46.95) 50.731,46.95 50.831,47.05 C863.2@51.625,47.05 ; C632.2@51.05,32.225 51.575,32.225 R631.1@51.6,32.2 51.625,32.175 v1(51.625,31.7) ; v1(51.214,43.449) 51.27,43.449 51.484,43.234 51.695,43.234 C909.2@51.705,43.224 ; R950.2@54.9,43.9 54.9,43.89 55.071,43.719 55.311,43.719 v1(55.35,43.679) ; C950.2@54.9,45.875 54.91,45.885 54.91,45.905 55.328,46.323 55.404,46.323 v1(55.444,46.362) ; C861.2@61.45,39.1 61.46,39.11 61.46,39.536 61.518,39.594 v1(61.518,39.65) ; U808.2@61.605,45.3 61.875,45.3 62.075,45.5 C808.2@62.075,46.85 ; v1(61.853,26.904) 61.86,26.904 R691.2@62.577,26.187 ; C860.2@62.4,37.1 62.773,37.1 62.819,37.145 v1(62.875,37.145) ; v1(62.45,30) Q807.4@63.125,30 ; U808.12@62.65,40.255 62.65,39.55 62.8,39.4 R852.1@62.8,39.25 ; v1(62.725,35.475) C800.2@63.1,35.85 ; Q807.1@64.425,29 64.425,28.25 R839.1@64.4,28.225 65.25,28.225 v1(65.4,28.375) C828.2@65.4,28.875 ; v1(65.2,26.921) 65.256,26.921 65.432,26.745 65.71,26.745 65.72,26.735 C653.2@65.72,26.715 ; C652.2@65.725,25.311 65.725,25.331 65.979,25.585 66.26,25.585 v1(66.3,25.625) ; v1(66.1,41.282) 66.138,41.244 66.476,41.244 C865.2@66.64,41.08 ; R688.2@67.486,27.233 67.496,27.233 67.506,27.243 67.506,27.55 67.8,27.844 v1(67.8,27.9) ; v1(67.625,32.2) 67.7,32.275 C866.2@67.7,32.725 ; R851.1@68.2,40.912 68.21,40.902 68.673,40.902 v1(68.7,40.875) ; R853.1@68.375,34.825 68.4,34.85 68.678,34.85 ; v1(68.7,34.025) 68.7,34.822 68.675,34.847 68.678,34.85 ; v1(68.8,30.3) 68.85,30.35 U810.7@69.45,30.35 ; v1(69.275,44.4) 69.45,44.225 U800.7@69.45,43.85 ; U806.7@69.45,34.85 68.678,34.85 ; U802.7@69.45,39.35 v1(69.45,39.825) ; C809.2@73.3,33.425 73.3,33.405 73.31,33.395 73.724,33.395 73.769,33.35 v1(73.825,33.35) ; C805.2@73.3,37.925 73.3,37.928 73.31,37.938 73.788,37.938 v1@73.811,37.961 ; D801.7@76.255,51.449 76.599,51.449 77.031,51.881 77.031,52.169 v1@77.057,52.195 ; v1(82.925,35.6) 82.962,35.563 82.962,35.162 C2.2@83.012,35.112 ; v1(84.25,51.425) D809.2@84.25,52.1 ; LED900.2@87.25,56.45 v1(87.25,57) ; v1(95.075,51.35) 95.2,51.475 D806.2@95.2,52 ; v1(96.692,51.031) 96.696,51.035 96.696,51.996 D807.2@96.7,52 ; R7.1@110.4,13.125 v1(110.4,13.775) ; C922.2@44.95,34.95 45.025,35.025 U910.3@46.225,35.025 47.625,35.025 v1(47.8,35.2) ; v1(45.475,31.175) 45.55,31.25 45.75,31.25 ; v1(45.475,31.175) 45.75,30.9 ; 45.75,30.9 45.75,31.25
  Top Layer w0.4: v1(80.775,35.775) 80.796,35.796 81.471,35.796 C1.2@81.675,36 81.4,36.275 80.904,36.275 80.829,36.35 v1(80.8,36.35) ; v1(81.9,30.6) C3.2@81.9,31.1
  Top Layer w0.5: v1(14.721,53.599) 14.722,53.601 15.451,53.601 C611.2@15.465,53.614 ; C607.2@18.782,53.072 C607.2@18.782,53.097 ; v1@19.478,52.377 19.523,52.377 v1(19.525,52.375) ; C714.2@25,38.55 v1(25,39.325) ; v1(31.925,38.75) R718.1@31.925,39.525 ; R771.1@32.2,42.6 32.2,42.625 32.621,43.046 32.621,43.269 32.75,43.398 v1(32.75,43.4) ; v1(81.25,30.6) C3.2@81.25,30.919 ; R113.1@90.342,5.037 90.351,5.037 90.743,4.645 v1(90.745,4.645) ; v1(97.55,56.325) 97.85,56.625 97.85,57.786 P801.7@97.905,57.841
  Top Layer w0.635: v1(72.765,56.325) 72.785,56.345 P800.19@72.785,57.95 ; v1(74.035,56.325) 74.055,56.345 P800.17@74.055,57.95 ; v1(75.305,56.325) 75.325,56.345 P800.15@75.325,57.95 ; v1(79.115,56.325) 79.135,56.345 P800.9@79.135,57.95 ; v1(81.655,56.325) 81.675,56.345 P800.5@81.675,57.95 ; v1(82.925,56.325) 82.945,56.345 P800.3@82.945,57.95 ; v1(92.811,56.325) 92.811,57.828 P801.15@92.825,57.841 ; v1(94.08,56.325) 94.105,56.325 94.095,56.335 P801.13@94.095,57.841 ; v1(95.35,56.325) 95.375,56.325 95.365,56.335 P801.11@95.365,57.841 ; v1@96.635,56.335 P801.9@96.635,57.841 ; v1(107.7,17.3) 107.7,18.253 108.018,18.57 P101.1@108.76,18.57 109.705,18.57 109.65,18.515 v1(109.65,17.35) v1(110.625,17.35)
  Top Layer w0.7: C607.2@18.782,53.072 v1@19.478,52.377
  Bottom Layer w0.25: v1(79.65,37.325) 80.1,37.325 R220.1@80.125,37.35 ; v1(79.65,38.65) 79.65,40.35 J204.2@79.675,40.375 ; J204.3@82.675,40.375 82.7,40.35 v1(82.7,38.65)
  Bottom Layer w0.3: TPJ614.1@7.6,49.725 7.61,49.715 8.535,49.715 v1(8.575,49.675)
  Bottom Layer w0.5: TPJ913.1@50.751,30.501 51.425,29.828 v1(51.425,29.575)
  Bottom Layer w0.508: 1.775,58.25 1.8,58.225 P601.25@1.8,56.82 ; 1.8,55.425 P601.25@1.8,56.82 ; v1@1.85,47.1 1.85,48.13 P601.26@1.8,48.18 ; 1.85,49.525 1.85,48.23 P601.26@1.8,48.18 ; 3.8,48.2 3.78,48.18 P601.26@1.8,48.18 ; 3.875,56.825 3.87,56.82 P601.25@1.8,56.82 ; 4.775,57 5.158,57 5.205,56.952 6.718,56.952 P601.27@6.85,56.82 ; 4.9,47.9 5.162,47.9 5.31,48.048 6.718,48.048 P601.28@6.85,48.18 P601.28@7.136,48.18 ; 6.95,58.1 6.85,58 P601.27@6.85,56.82 ; 7.1,46.75 P601.28@7.1,47.93 ; v1@7.125,55.725 7.125,56.545 P601.27@6.85,56.82 ; TPJ614.1@7.55,49.8 7.55,49.67 7.136,49.256 P601.28@7.136,48.18 ; 8.825,56.9 6.93,56.9 P601.27@6.85,56.82 ; 9.125,48.35 8.955,48.18 P601.28@7.136,48.18
  other v1: 31.877,1.101 20.829,1.138 6.027,1.176 8.45,1.2 96.452,1.201 99.877,1.201 10.552,1.226 26.827,1.226 37.352,1.226 103.052,1.226 106.002,1.226 109.152,1.226 15.077,1.251 57.552,1.251 62.727,1.251 72.952,1.251 89.627,1.251 93.002,1.251 42.527,1.276 47.452,1.276 52.525,1.275 86.227,1.276 82.777,1.326 79.402,1.376 70.402,1.476 76.127,1.501 1.152,1.801 60.2,2.4 65.3,2.4 28.25,2.8 101,3 82.5,3.5 17.089,4.132 108.875,4.125 32.2,4.5 37.3,4.5 42.4,4.5 1.177,4.901 70.475,5.1 113.977,5.751 111,6.15 99.057,6.199 105.282,6.274 66.207,7.174 51.373,7.453 112.5,7.5 114.002,7.526 44.257,7.549 48.982,7.549 64.332,7.549 54.532,7.574 62.257,7.624 57.607,7.749 59.707,7.774 20.841,8.257 101.207,9.599 47.757,9.674 39.012,10.126 114.002,10.401 28,11 45.807,10.999 32.732,11.324 22.132,11.549 71.307,12.074 80.057,12.149 61.3,12.225 58.682,12.249 63.957,12.274 57.207,12.974 50.225,13.15 48.207,13.424 63.982,13.899 60.232,13.949 114.052,14.201 90.232,14.249 35.057,14.524 30.482,14.699 54.007,14.749 20.182,14.899 83.5,15.45 94.5,15.5 112.5,15.5 99.982,15.574 6.05,15.925 7.075,15.925 46.807,15.949 8.1,15.975 64.032,16.074 58.832,16.824 6,16.925 7.025,16.925 8.125,16.975 114.025,17.375 39.5,17.5 56.882,17.824 45.007,17.924 5.975,17.975 7,18 8.025,18 49.775,18 60.5,18.5 22.107,18.524 32.132,18.524 36.482,18.549 28.019,18.658 92.932,18.674 75.982,18.849 89.475,19.4 53.082,19.524 19.732,19.574 45.275,19.875 69.1,20.1 97.225,20.4 100.8,20.4 57.123,21.229 61.382,21.374 27.032,21.474 50.625,21.475 64.082,21.474 66.732,21.474 89.449,21.67 21.207,22.499 78.625,22.75 100.775,23.3 98.137,23.337 88.9,23.375 70.032,23.449 74.327,23.831 90.857,24.274 100,24.3 111.3,24.8 18.1,25.4 73.455,25.44 77.957,25.449 33.652,26.011 84.263,26.047 49.398,26.329 95.732,26.549 45.998,26.604 101.95,26.65 91.1,26.7 25.157,26.799 113.977,27.451 15.15,27.625 53.175,28.05 85.957,28.049 33.907,28.124 100.5,28.3 19.757,28.349 75.957,28.349 1.775,28.875 68.575,29.2 24.857,29.224 27.732,29.399 74.682,29.474 90.91,30.339 73.825,30.4 54.934,30.434 17.657,30.699 5.157,30.824 31.65,30.95 32.6,30.95 61.25,31.075 64.05,31.225 26.382,31.249 53.825,31.45 31.65,31.575 32.6,31.575 93.3,31.775 79.907,31.924 1.8,31.925 96.5,32.1 7.907,32.174 101.5,32.2 21.432,32.274 60.923,32.354 83.6,32.425 114.102,32.476 76.132,32.599 89.725,32.7 28.082,33.149 5.107,33.474 85.5,33.9 86.6,33.9 87.7,33.9 62.625,34.025 19.682,34.399 93.5,34.775 97.325,34.8 102,34.825 85.5,35 86.6,35 87.7,35 111.4,35 7.65,35.05 1.775,35.075 79.082,35.549 75.922,35.777 85.5,36.1 86.6,36.1 87.7,36.1 17.644,36.526 25.609,36.54 21.957,37.249 89.6,37.475 114.102,37.651 27.782,37.699 84.25,37.95 32.999,37.971 92.525,38.375 96.832,38.549 46.925,38.625 100.15,38.775 29.373,39.028 28.375,39.075 77.331,39.477 21,39.5 51.075,39.5 29.373,39.903 28.375,39.95 62.8,41.575 64,41.575 20.119,41.633 17.95,41.825 22.325,41.825 33.35,41.825 34.475,41.825 13,42 16,42.125 4.582,42.774 8.157,42.824 1.725,42.875 77.657,42.874 114.002,42.901 47.925,42.925 62.8,43 64,43 100.675,43.1 17.95,43.125 20.125,43.125 22.3,43.125 28.65,43.125 33.425,43.125 34.475,43.125 16.775,43.2 14.6,43.525 110.8,44.175 73.5,44.3 15.6,44.375 76.332,44.524 62.8,44.55 64,44.55 94.274,44.686 13.25,44.85 33.282,44.828 6.407,44.874 28.565,44.856 22.464,44.924 66.275,45.575 79.75,45.575 113.977,45.576 14.3,45.675 112.007,46.049 97.4,46.15 11.9,46.2 1.775,46.35 89.5,46.425 2.74,46.918 5.5,46.925 8.075,46.925 109.032,46.924 3.525,46.975 6.79,46.968 0.915,46.993 12.975,47 1.915,47.043 11.65,47.5 22.557,47.499 4.465,47.543 42.875,47.75 8.715,47.893 114.002,47.976 14,48 36.675,48.025 39.375,48.025 12.95,48.2 13.548,48.753 8.725,48.8 63.432,48.924 57.633,49.118 104.375,49.1 111.207,49.149 106.332,49.174 25.007,49.424 12.95,49.45 66.575,49.475 11.625,49.55 67.929,49.533 61.232,49.69 59.408,49.868 33.157,50.024 93.825,50.475 23.307,50.549 113.977,50.551 100.875,51.025 20.357,51.249 12.95,51.3 41.207,51.399 101.75,51.534 108.582,51.699 31.907,51.749 28.232,51.849 67.8,53.4 113.927,53.426 18.757,54.672 47.2,55 18.492,55.167 34.9,55.2 32.2,55.3 52.5,55.3 25.382,55.424 18.17,55.635 96.6,56.325 8.74,56.468 8.565,57.318 104,57.5 3.615,57.518 4.565,57.543 5.54,57.743 6.54,57.993 1.19,58.043 3.14,58.093 86.8,58.1 2.244,58.175 7.911,58.172 103.652,58.876 106.477,58.901 109.152,58.901 1.177,59.001 5.177,59.001 89.202,58.976 9.327,59.026 86.802,59.026 22.1,59.05 35.052,59.051 44.877,59.051 57.552,59.051 62.502,59.051 13.352,59.076 17.927,59.076 26.475,59.075 39.727,59.076 52.602,59.076 71.627,59.076 30.077,59.101 67.827,59.101 48.877,59.126
JS_A: R125.2 SW105.1 | length 1.5
  Top Layer w0.1: SW105.1@88.57,5.464 89.612,4.423 R125.2@89.612,4.412
JS_B: R126.2 SW105.3 | length 1.7
  Top Layer w0.1: SW105.3@90.586,7.48 91.253,6.812 R126.2@92.012,6.812
JS_C: R127.2 SW105.6 | length 1.6
  Top Layer w0.1: R127.2@84.612,13.712 85.53,12.795 SW105.6@85.53,12.536
JS_CEN: R113.2 SW105.2 | length 1.7
  Top Layer w0.1: SW105.2@89.578,6.472 89.618,6.472 90.14,5.95 90.701,5.95 R113.2@90.978,5.673
JS_D: R124.2 SW105.4 | length 1.6
  Top Layer w0.1: R124.2@82.612,11.712 83.514,10.81 SW105.4@83.514,10.52
LED_JLINK: LED901.2 TPJ912.1 U900.A7 | length 52.5
  Top Layer w0.1: v1(46.425,38.275) 46.425,38.864 46.643,39.082 46.643,40.007 46.525,40.125 46.525,40.575 46.6,40.65 U900.A7@46.6,41.5
  Top Layer w0.2: v1(15.051,50.534) 15.051,49.826 LED901.2@15.075,49.85 ; LED901.2@15.075,49.85 15.205,49.98 15.2,49.98 15.075,49.855 LED901.2@15.075,49.85
  Signal Layer 3 w0.1: v1@15.057,50.527 16.875,48.709 16.875,45.625 22.075,40.425 25.296,40.425 26.321,41.45 31.125,41.45 33.775,38.8 41.075,38.8 41.575,39.3 43.525,39.3 44.64,38.185 45.135,38.185 45.175,38.225 46.375,38.225 v1(46.425,38.275)
  Bottom Layer w0.1: v1(46.425,38.275) 46.425,38.75 46.775,39.1 48.35,39.1 48.925,38.525 48.925,36.051 TPJ912.1@50.751,34.225
LED_STATUS_G: LED904.3 U900.D13 | length 30.4
  Top Layer w0.1: v1(41.225,42.45) 41.25,42.475 41.8,42.475 42.325,43 U900.D13@43.6,43
  Top Layer w0.2: LED904.3@21.15,49.75 v1(21.85,49.75)
  Signal Layer 3 w0.1: v1(21.85,49.75) 20.525,48.425 20.525,45.725 22.225,44.025 36.675,44.025 38.818,41.882 39.807,41.882 40.3,42.375 41.175,42.375 41.175,42.4 v1(41.225,42.45)
LED_STATUS_R: LED904.4 U900.E13 | length 28.8
  Top Layer w0.1: v1(39.304,43.07) 39.304,43.018 39.671,42.65 40.575,42.65 40.968,43.043 41.768,43.043 42.225,43.5 U900.E13@43.6,43.5
  Top Layer w0.2: LED904.4@21.15,49.05 v1(21.85,49.05)
  Signal Layer 3 w0.1: v1(21.85,49.05) 20.85,48.05 20.85,45.8 22.325,44.325 36.833,44.325 38.087,43.07 v1(39.304,43.07)
MCU_P0.0: J102.3 P101.3 R5.2 | length 106.4
  Top Layer w0.1: R5.2@83.212,37.287 83.4,37.475 v1(83.4,38.3) ; v1(106.712,22.362) 106.712,22.283 107.886,21.11 P101.3@108.76,21.11
  Signal Layer 3 w0.1: v1(83.4,38.3) 84.85,39.75 v1(87.925,39.75) ; v1(91.275,29.375) 103.9,29.375 107.725,25.55 107.725,23.374 v1@106.75,22.399
  Signal Layer 4 w0.1: J102.3@36.03,56.602 37.628,58.2 51.225,58.2 51.5,57.925 75.997,57.925 82.569,51.353 82.786,51.353 83.1,51.039 83.1,49.925 84.143,48.882 84.143,39.043 v1(83.4,38.3) ; v1@87.975,39.8 87.975,39.679 88.2,39.454 88.2,37.754 89.282,36.672 89.282,31.368 v1(91.275,29.375)
MCU_P0.1: J102.4 R301.2 R302.2 U1.1 | length 68.8
  Top Layer w0.1: J102.4@38.57,56.602 37.7,55.732 37.7,53.825 38.6,52.925 R301.2@38.6,52.564 ; R301.2@38.625,52.5 38.689,52.564 R302.2@39.546,52.564 ; v1(83.75,39.65) 83.75,38.75 83.85,38.65 83.85,36.65 84,36.5 U1.1@84.325,36.5
  Signal Layer 4 w0.1: J102.4@38.57,56.602 39.968,58 51.125,58 51.4,57.725 75.875,57.725 82.23,51.37 82.23,50.797 82.8,50.228 82.8,49.825 83.9,48.725 83.9,40.275 83.75,40.125 v1(83.75,39.65)
MCU_P0.2: C102.1 J102.5 R100.1 SW100.3 SW100.4 TPJ652.1 U1.28 U950.8 | length 155.2
  Top Layer w0.1: C102.1@50.45,11.725 50.475,11.7 51.7,11.7 SW100.3@51.925,11.925 SW100.4@56.075,11.925 v1(57.075,11.925) ; v1(52.083,44.246) 52.375,44.246 52.425,44.196 U950.8@52.425,44.015 ; U1.28@85.1,37.275 v1(85.1,38.225)
  Signal Layer 3 w0.1: J102.5@41.11,56.602 42.937,54.775 43.925,54.775 46.45,52.25 69.375,52.25 70.125,51.5 80.2,51.5 80.839,52.139 82.943,52.139 v1(83.52,51.562) ; v1(57.075,11.925) 58.45,13.3 69.625,13.3 70.45,14.125 74.85,14.125 82.225,21.5 v1(82.225,22.125)
  Signal Layer 4 w0.1: v1(52.083,44.246) 53.654,42.675 53.654,41.921 54.475,41.1 54.475,37.425 55.693,36.207 55.693,17.043 55.025,16.375 55.025,13.975 v1(57.075,11.925) ; v1(82.225,22.125) 82.225,28.456 84.025,30.256 84.025,37.15 v1(85.1,38.225) 85.1,38.85 84.4,39.55 84.4,49.1 83.52,49.98 v1(83.52,51.562)
  Bottom Layer w0.1: v1(57.075,11.925) 57.1,11.9 TPJ652.1@61.303,16.102
MCU_P0.3: C103.1 J102.6 R101.1 SW101.3 SW101.4 TPJ653.1 U1.27 U950.11 | length 118.8
  Top Layer w0.1: R101.1@38.404,11.758 R101.1@38.429,11.733 38.441,11.745 38.97,11.745 C103.1@38.975,11.75 ; C103.1@38.986,11.756 39.756,11.756 SW101.3@39.925,11.925 SW101.4@44.075,11.925 v1(45.075,11.925) ; U950.11@53.625,44.015 53.625,43.318 54.062,42.881 54.062,42.406 v1(54.047,42.39) ; U1.27@85.6,37.275 v1(85.6,38.725)
  Signal Layer 3 w0.1: v1(45.075,11.925) 49.25,16.1 v1(51.05,16.1) 51.06,16.09 55.534,16.09 v1(55.544,16.08) 55.564,16.1 59.275,16.1 59.9,16.725 76.825,16.725 81.325,21.225 81.325,22.075 82,22.75 82.587,22.75 82.837,22.5 v1(82.875,22.5)
  Signal Layer 4 w0.1: J102.6@43.65,56.602 43.65,56.5 47.225,52.925 47.225,48.169 48.212,47.182 50.338,47.182 50.499,47.343 51.007,47.343 51.6,46.75 51.6,46.5 52.7,45.4 52.7,44.254 54.089,42.865 54.089,42.432 v1(54.047,42.39) ; v1@54.062,42.405 54.086,42.382 54.086,41.86 54.725,41.221 54.725,37.525 55.893,36.357 55.893,16.429 v1(55.544,16.08) ; v1(82.875,22.5) 82.875,28.375 84.275,29.775 84.275,36.8 85.6,38.125 v1(85.6,38.725)
  Bottom Layer w0.1: v1(51.05,16.1) 51.052,16.102 TPJ653.1@51.953,16.102
MCU_P0.4: J102.7 U1.26 U812.2 | length 89.8
  Top Layer w0.1: v1(66.65,28.5) 66.625,28.5 66.7,28.575 U812.2@66.7,29.165 ; U1.26@86.1,37.275 v1(86.1,38.225)
  Signal Layer 3 w0.1: J102.7@46.19,56.602 50.292,52.5 69.6,52.5 70.325,51.775 80.125,51.775 80.775,52.425 84.556,52.425 85.85,51.131 v1(85.85,50.375) ; v1(66.65,28.5) 66.65,27.075 67.175,26.55 82.425,26.55 v1(83.45,25.525)
  Signal Layer 4 w0.1: v1(83.45,25.525) 83.45,28.275 84.5,29.325 84.5,36.625 v1(86.1,38.225) 86.1,49.525 85.85,49.775 v1(85.85,50.375)
MCU_P0.5: J102.8 U1.25 U812.4 | length 97.3
  Top Layer w0.1: U812.4@67.5,29.165 67.5,28.5 67.581,28.419 v1(68.138,28.419) ; U1.25@86.6,37.275 86.6,37.982 86.7,38.082 v1(86.7,38.675)
  Signal Layer 3 w0.1: J102.8@48.73,56.602 50.728,58.6 v1(85.6,58.6) ; v1(68.138,28.419) 68.961,28.419 70.524,26.857 90.168,26.857 v1(90.175,26.85)
  Signal Layer 4 w0.1: v1(85.6,58.6) 85.275,58.275 85.275,51.506 86.4,50.381 86.4,39.575 86.7,39.275 86.7,38.069 87.069,37.7 87.525,37.7 88.85,36.375 88.85,30.975 90.175,29.65 v1(90.175,26.85)
MCU_P1.7: C106.1 J101.11 R111.1 SW105.5 U1.15 | length 61.2
  Top Layer w0.1: v1(79.475,14.7) 81.625,14.7 v1(82.8,13.525) 83.212,13.113 84.522,11.802 SW105.5@84.522,11.528 ; U1.15@88.875,33.5 88.888,33.487 89.962,33.487 v1(89.975,33.475)
  Signal Layer 3 w0.1: J101.11@56.35,3.262 61.988,8.9 73.775,8.9 79.475,14.6 v1(79.475,14.7)
  Signal Layer 4 w0.1: v1(82.8,13.525) 86.15,16.875 88.2,16.875 91.775,20.45 91.775,31.675 v1(89.975,33.475)
MCU_P2.0: J101.10 R304.2 U1.14 | length 59.2
  Top Layer w0.1: R304.2@52.502,7.502 52.525,7.479 52.525,4.65 53.81,3.365 J101.10@53.81,3.262 ; U1.14@88.1,32.725 88.1,31.675 88.285,31.49 v1(88.285,30.665)
  Signal Layer 3 w0.1: J101.10@53.81,3.262 59.798,9.25 73.45,9.25 82.3,18.1 86.725,18.1 v1(87.85,19.225)
  Signal Layer 4 w0.1: v1(87.85,19.225) 87.85,29.45 88.285,29.885 v1(88.285,30.665)
MCU_P3.0: J101.5 R305.2 | length 5.6
  Top Layer w0.1: R305.2@41.15,7.5 40.5,7.5 39.75,6.75 39.75,4.875 J101.5@41.2,3.425
N16831167: R700.1 U701.7 | length 1
  Top Layer w0.2: U701.7@32.375,30.125 32.375,29.473 32.627,29.221 R700.1@32.627,29.211
N16831188: C705.1 U701.6 | length 1
  Top Layer w0.2: U701.6@31.875,30.125 31.875,29.374 32.05,29.199 C705.1@32.05,29.179
N16831199: R702.1 R703.2 U701.5 | length 2.4
  Top Layer w0.2: R703.2@30.1,30.125 U701.5@31.375,30.125 31.375,29.18 R702.1@31.216,29.021
N16831281: R705.2 TP711.1 U702.11 | length 4.1
  Top Layer w0.1: v1(39.421,35.535) 39.452,35.566 39.452,35.939 39.993,36.479 40.213,36.259 41.799,36.259 U702.11@41.815,36.275
  Bottom Layer w0.1: v1(39.421,35.535) 39.421,35.424 39.528,35.318 39.528,34.872 TP711.1@39.7,34.7
N16831285: R706.2 TP712.1 U702.8 | length 2.8
  Top Layer w0.1: v1(40.35,38.194) 40.42,38.124 40.42,37.959 40.5,37.878 R706.2@40.855,37.878 ; R706.2@40.87,37.894 R706.2@40.855,37.878 ; U702.8@41.815,37.475 41.289,37.475 40.885,37.878 R706.2@40.855,37.878
  Bottom Layer w0.1: TP712.1@39.7,38.8 39.722,38.8 40.328,38.194 v1(40.35,38.194)
N16831289: R707.2 TP713.1 U702.3 | length 2.9
  Top Layer w0.1: U702.3@43.585,36.675 44.458,36.675 44.523,36.739 44.638,36.624 v1(45.104,36.624)
  Bottom Layer w0.1: TP713.1@43.8,36.7 43.838,36.662 45.065,36.662 v1(45.104,36.624)
N16831309: R708.2 TP714.1 U702.1 | length 2.8
  Top Layer w0.1: v1(43.625,35.475) 43.625,35.5 43.585,35.54 U702.1@43.585,35.875 44.3,35.875 R708.2@44.4,35.775
  Bottom Layer w0.1: TP714.1@43.2,34.1 43.2,35.05 v1(43.625,35.475)
N16831821: C707.1 L702.2 U702.14 | length 1.9
  Top Layer w0.2: C707.1@42.85,34.975 42.9,35.025 U702.14@42.9,35.79
  Top Layer w0.3: L702.2@42.435,34.05 42.85,34.465 C707.1@42.85,34.975
N17207915: LED2.4 R135.1 | length 0.9
  Top Layer w0.2: LED2.4@68.925,12.575 69.725,12.575 R135.1@69.8,12.65
N17207930: LED2.3 R136.1 | length 0.9
  Top Layer w0.1: LED2.3@68.925,13.425 68.925,14.266 R136.1@68.944,14.284
N17207934: LED2.2 R137.1 | length 0.9
  Top Layer w0.1: R137.1@68.052,14.287 68.075,14.264 LED2.2@68.075,13.425
N17208223: P100.3 R145.1 R146.2 | length 11.8
  Top Layer w0.1: P100.3@46.25,30.175 46.25,29.625 46.775,29.1 46.775,28.475 48,27.25 49.15,27.25 50.175,28.275 50.175,28.875 50.372,29.072 53.817,29.072 R145.1@54.007,28.882 R146.2@54.932,28.882 ; R145.1@54,28.7 R145.1@54.007,28.693
N17208307: P100.10 TP150.1 U100.16 | length 14.6
  Top Layer w0.1: v1(39.304,31.894) 39.406,31.894 39.675,31.625 39.74,31.625 39.79,31.575 U100.16@39.79,31.375 ; v1(49.75,29.125) P100.10@49.75,30.175
  Signal Layer 3 w0.1: v1(39.304,31.894) 40.023,31.175 41.985,31.175 43.385,29.775 49.1,29.775 v1(49.75,29.125)
  Bottom Layer w0.1: TP150.1@38.3,32.3 38.544,32.3 38.9,31.944 39.254,31.944 v1(39.304,31.894)
N17208309: P100.9 TP151.1 U100.4 | length 14.8
  Top Layer w0.1: v1(39.492,27.925) 39.492,29.525 39.542,29.575 U100.4@39.59,29.575 ; v1(49.25,28.25) P100.9@49.25,30.175
  Signal Layer 3 w0.1: v1(39.492,27.925) 40.818,27.925 40.918,28.025 48.325,28.025 48.55,28.25 v1(49.25,28.25)
  Bottom Layer w0.1: TP151.1@38.3,27.8 38.362,27.862 39.43,27.862 v1(39.492,27.925)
